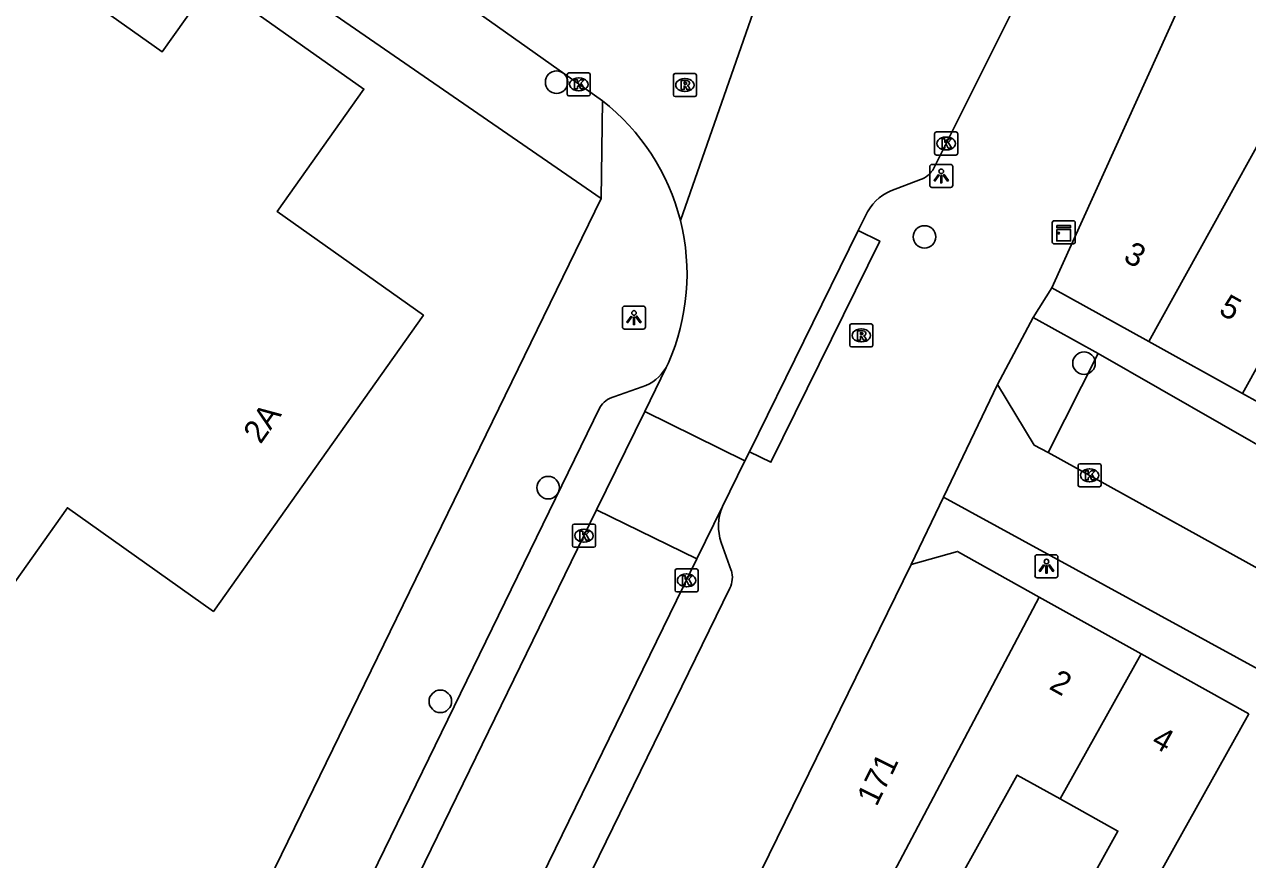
# Model space of a CAD drawing. Extents: x 160107 to 160928, y 382056 to 382918.
# Drawn here: x 160268.4 to 160321.6, y 382212 to 382248.3 of the extents above; entities that cross this region are included whole.
import ezdxf

# ---------------------------------------------------------------- set-up
doc = ezdxf.new("R2010")
doc.units = 0
for name, color, linetype in [('IMGEO_Boom', 7, 'Continuous'), ('IMGEO_Kast', 7, 'Continuous'), ('IMGEO_Kolk', 7, 'Continuous'), ('IMGEO_Lichtpunt', 7, 'Continuous'), ('IMGEO_Pand', 7, 'Continuous'), ('IMGEO_Pand_nummerreeks', 7, 'Continuous'), ('IMGEO_Parkeervlak_open', 7, 'Continuous'), ('IMGEO_Rijbaan_lokaal_open', 7, 'Continuous'), ('IMGEO_Rioolput', 7, 'Continuous'), ('IMGEO_Voetpad_open', 7, 'Continuous'), ('IMGEO_Woonerf_open', 7, 'Continuous')]:
    doc.layers.add(name, color=color, linetype=linetype)

msp = doc.modelspace()

# ---------------------------------------------------------------- linework, layer by layer
at = {"layer": 'IMGEO_Boom'}
for centre in [(160291.537, 382245.757), (160307.521, 382239.035), (160314.452, 382233.55), (160291.168, 382228.146), (160286.485, 382218.864)]:
    msp.add_circle(centre, 0.489, dxfattribs=at)
at = {"layer": 'IMGEO_Kast'}
for p, q in [((160313.072, 382238.813), (160313.072, 382239.654)), ((160313.072, 382239.654), (160313.072, 382238.813)), ((160313.147, 382239.738), (160313.988, 382239.738)), ((160313.988, 382239.738), (160313.147, 382239.738)), ((160314.072, 382239.663), (160314.072, 382238.822)), ((160314.072, 382238.822), (160314.072, 382239.663)), ((160313.997, 382238.738), (160313.156, 382238.738)), ((160313.156, 382238.738), (160313.997, 382238.738))]:
    msp.add_line(p, q, dxfattribs=at)
for points in [[(160313.267, 382239.528), (160313.867, 382239.528), (160313.867, 382239.443), (160313.267, 382239.443), (160313.267, 382239.528)], [(160313.267, 382239.353), (160313.867, 382239.353), (160313.867, 382238.864), (160313.267, 382238.864), (160313.267, 382239.353)]]:
    msp.add_lwpolyline(points, dxfattribs=at)
msp.add_circle((160313.351, 382239.202), 0.0377, dxfattribs=at)
for centre, start, end in [((160313.15, 382239.66), 92.4484, 184.2845), ((160313.15, 382239.66), 92.4484, 184.2845), ((160313.994, 382239.66), 2.4484, 94.2845), ((160313.994, 382239.66), 2.4484, 94.2845), ((160313.15, 382238.816), 182.4484, 274.2845), ((160313.15, 382238.816), 182.4484, 274.2845), ((160313.994, 382238.816), 272.4484, 4.2845), ((160313.994, 382238.816), 272.4484, 4.2845)]:
    msp.add_arc(centre, 0.0779, start, end, dxfattribs=at)
at = {"layer": 'IMGEO_Kolk'}
for p, q in [((160291.999, 382245.236), (160291.999, 382246.088)), ((160292.074, 382246.162), (160292.926, 382246.162)), ((160292.487, 382245.942), (160292.512, 382245.942)), ((160293, 382246.088), (160293, 382245.236)), ((160292.51, 382245.382), (160292.485, 382245.382)), ((160292.926, 382245.162), (160292.074, 382245.162)), ((160307.962, 382242.667), (160307.962, 382243.519)), ((160308.037, 382243.593), (160308.889, 382243.593)), ((160308.45, 382243.373), (160308.475, 382243.373)), ((160308.963, 382243.519), (160308.963, 382242.667)), ((160308.473, 382242.813), (160308.448, 382242.813)), ((160308.889, 382242.593), (160308.037, 382242.593)), ((160314.195, 382228.256), (160314.195, 382229.108)), ((160314.27, 382229.182), (160315.122, 382229.182)), ((160314.683, 382228.962), (160314.708, 382228.962)), ((160315.196, 382229.108), (160315.196, 382228.256)), ((160314.706, 382228.402), (160314.681, 382228.402)), ((160315.122, 382228.182), (160314.27, 382228.182)), ((160292.226, 382225.634), (160292.226, 382226.486)), ((160292.301, 382226.56), (160293.153, 382226.56)), ((160292.714, 382226.34), (160292.739, 382226.34)), ((160293.227, 382226.486), (160293.227, 382225.634)), ((160292.737, 382225.78), (160292.712, 382225.78)), ((160293.153, 382225.56), (160292.301, 382225.56)), ((160296.683, 382223.691), (160296.683, 382224.543)), ((160296.758, 382224.617), (160297.61, 382224.617)), ((160297.171, 382224.397), (160297.196, 382224.397)), ((160297.684, 382224.543), (160297.684, 382223.691)), ((160297.61, 382223.617), (160296.758, 382223.617)), ((160297.194, 382223.837), (160297.169, 382223.837))]:
    msp.add_line(p, q, dxfattribs=at)
for points in [[(160291.999, 382245.236), (160291.999, 382246.088)], [(160292.074, 382246.162), (160292.926, 382246.162)], [(160293, 382246.088), (160293, 382245.236)], [(160292.32, 382245.862), (160292.443, 382245.862), (160292.443, 382245.711), (160292.573, 382245.862), (160292.737, 382245.862), (160292.591, 382245.711), (160292.744, 382245.462), (160292.592, 382245.462), (160292.507, 382245.626), (160292.443, 382245.559), (160292.443, 382245.462), (160292.32, 382245.462), (160292.32, 382245.862)], [(160292.926, 382245.162), (160292.074, 382245.162)], [(160307.962, 382242.667), (160307.962, 382243.519)], [(160308.037, 382243.593), (160308.889, 382243.593)], [(160308.283, 382243.293), (160308.406, 382243.293), (160308.406, 382243.142), (160308.536, 382243.293), (160308.7, 382243.293), (160308.554, 382243.142), (160308.707, 382242.893), (160308.555, 382242.893), (160308.47, 382243.057), (160308.406, 382242.99), (160308.406, 382242.893), (160308.283, 382242.893), (160308.283, 382243.293)], [(160308.963, 382243.519), (160308.963, 382242.667)], [(160308.889, 382242.593), (160308.037, 382242.593)], [(160314.195, 382228.256), (160314.195, 382229.108)], [(160314.27, 382229.182), (160315.122, 382229.182)], [(160315.196, 382229.108), (160315.196, 382228.256)], [(160314.516, 382228.882), (160314.639, 382228.882), (160314.639, 382228.731), (160314.769, 382228.882), (160314.933, 382228.882), (160314.787, 382228.731), (160314.94, 382228.482), (160314.788, 382228.482), (160314.703, 382228.646), (160314.639, 382228.579), (160314.639, 382228.482), (160314.516, 382228.482), (160314.516, 382228.882)], [(160315.122, 382228.182), (160314.27, 382228.182)], [(160292.226, 382225.634), (160292.226, 382226.486)], [(160292.301, 382226.56), (160293.153, 382226.56)], [(160292.547, 382226.26), (160292.67, 382226.26), (160292.67, 382226.109), (160292.8, 382226.26), (160292.964, 382226.26), (160292.818, 382226.109), (160292.971, 382225.86), (160292.819, 382225.86), (160292.734, 382226.024), (160292.67, 382225.957), (160292.67, 382225.86), (160292.547, 382225.86), (160292.547, 382226.26)], [(160293.227, 382226.486), (160293.227, 382225.634)], [(160293.153, 382225.56), (160292.301, 382225.56)], [(160296.683, 382223.691), (160296.683, 382224.543)], [(160296.758, 382224.617), (160297.61, 382224.617)], [(160297.004, 382224.317), (160297.127, 382224.317), (160297.127, 382224.166), (160297.257, 382224.317), (160297.421, 382224.317), (160297.275, 382224.166), (160297.428, 382223.917), (160297.276, 382223.917), (160297.191, 382224.081), (160297.127, 382224.014), (160297.127, 382223.917), (160297.004, 382223.917), (160297.004, 382224.317)], [(160297.684, 382224.543), (160297.684, 382223.691)], [(160297.61, 382223.617), (160296.758, 382223.617)]]:
    msp.add_lwpolyline(points, dxfattribs=at)
for centre, start, end in [((160292.076, 382246.086), 91.552, 178.448), ((160292.076, 382246.086), 91.552, 178.448), ((160292.924, 382246.086), 1.552, 88.448), ((160292.924, 382246.086), 1.552, 88.448), ((160292.076, 382245.238), 181.552, 268.448), ((160292.076, 382245.238), 181.552, 268.448), ((160292.924, 382245.238), 271.552, 358.448), ((160292.924, 382245.238), 271.552, 358.448), ((160308.039, 382243.517), 91.552, 178.448), ((160308.039, 382243.517), 91.552, 178.448), ((160308.887, 382243.517), 1.552, 88.448), ((160308.887, 382243.517), 1.552, 88.448), ((160308.039, 382242.669), 181.552, 268.448), ((160308.039, 382242.669), 181.552, 268.448), ((160308.887, 382242.669), 271.552, 358.448), ((160308.887, 382242.669), 271.552, 358.448), ((160314.272, 382229.106), 91.552, 178.448), ((160314.272, 382229.106), 91.552, 178.448), ((160315.12, 382229.106), 1.552, 88.448), ((160315.12, 382229.106), 1.552, 88.448), ((160314.272, 382228.258), 181.552, 268.448), ((160314.272, 382228.258), 181.552, 268.448), ((160315.12, 382228.258), 271.552, 358.448), ((160315.12, 382228.258), 271.552, 358.448), ((160292.303, 382226.484), 91.552, 178.448), ((160292.303, 382226.484), 91.552, 178.448), ((160293.151, 382226.484), 1.552, 88.448), ((160293.151, 382226.484), 1.552, 88.448), ((160292.303, 382225.636), 181.552, 268.448), ((160292.303, 382225.636), 181.552, 268.448), ((160293.151, 382225.636), 271.552, 358.448), ((160293.151, 382225.636), 271.552, 358.448), ((160296.76, 382224.541), 91.552, 178.448), ((160296.76, 382224.541), 91.552, 178.448), ((160297.608, 382224.541), 1.552, 88.448), ((160297.608, 382224.541), 1.552, 88.448), ((160296.76, 382223.693), 181.552, 268.448), ((160296.76, 382223.693), 181.552, 268.448), ((160297.608, 382223.693), 271.552, 358.448), ((160297.608, 382223.693), 271.552, 358.448)]:
    msp.add_arc(centre, 0.0765, start, end, dxfattribs=at)
for centre, major_axis, ratio, start_param, end_param in [((160292.486, 382245.662), (-0.387, 0.002), 0.722429, 4.712389, 7.853982), ((160292.511, 382245.662), (-0.39, 0.002), 0.717154, 1.570796, 4.712389), ((160308.449, 382243.093), (-0.387, 0.002), 0.722429, 4.712389, 7.853982), ((160308.474, 382243.093), (-0.39, 0.002), 0.717154, 1.570796, 4.712389), ((160314.682, 382228.682), (-0.387, 0.002), 0.722429, 4.712389, 7.853982), ((160314.707, 382228.682), (-0.39, 0.002), 0.717154, 1.570796, 4.712389), ((160292.713, 382226.06), (-0.387, 0.002), 0.722429, 4.712389, 7.853982), ((160292.738, 382226.06), (-0.39, 0.002), 0.717154, 1.570796, 4.712389), ((160297.17, 382224.117), (-0.387, 0.002), 0.722429, 4.712389, 7.853982), ((160297.195, 382224.117), (-0.39, 0.002), 0.717154, 1.570796, 4.712389)]:
    msp.add_ellipse(centre, major_axis=major_axis, ratio=ratio, start_param=start_param, end_param=end_param, dxfattribs=at)
at = {"layer": 'IMGEO_Lichtpunt'}
for p, q in [((160308.653, 382242.182), (160307.845, 382242.182)), ((160308.653, 382242.182), (160307.845, 382242.182)), ((160307.751, 382242.087), (160307.751, 382241.28)), ((160307.751, 382242.087), (160307.751, 382241.28)), ((160308.747, 382241.28), (160308.747, 382242.087)), ((160308.747, 382241.28), (160308.747, 382242.087)), ((160307.845, 382241.186), (160308.653, 382241.186)), ((160307.845, 382241.186), (160308.653, 382241.186)), ((160294.399, 382235.935), (160294.399, 382235.128)), ((160294.399, 382235.935), (160294.399, 382235.128)), ((160295.301, 382236.03), (160294.493, 382236.03)), ((160295.301, 382236.03), (160294.493, 382236.03)), ((160295.395, 382235.128), (160295.395, 382235.935)), ((160295.395, 382235.128), (160295.395, 382235.935)), ((160294.493, 382235.034), (160295.301, 382235.034)), ((160294.493, 382235.034), (160295.301, 382235.034)), ((160313.225, 382225.231), (160312.417, 382225.231)), ((160313.225, 382225.231), (160312.417, 382225.231)), ((160312.323, 382225.136), (160312.323, 382224.329)), ((160312.323, 382225.136), (160312.323, 382224.329)), ((160313.319, 382224.329), (160313.319, 382225.136)), ((160313.319, 382224.329), (160313.319, 382225.136)), ((160312.417, 382224.235), (160313.225, 382224.235)), ((160312.417, 382224.235), (160313.225, 382224.235))]:
    msp.add_line(p, q, dxfattribs=at)
for points in [[(160308.125, 382241.751), (160308.164, 382241.723), (160307.976, 382241.461), (160307.938, 382241.488), (160308.125, 382241.751)], [(160308.227, 382241.703), (160308.274, 382241.703), (160308.274, 382241.381), (160308.227, 382241.381), (160308.227, 382241.703)], [(160308.337, 382241.723), (160308.375, 382241.75), (160308.562, 382241.488), (160308.523, 382241.46), (160308.337, 382241.723)], [(160294.773, 382235.599), (160294.812, 382235.571), (160294.624, 382235.309), (160294.586, 382235.336), (160294.773, 382235.599)], [(160294.875, 382235.551), (160294.922, 382235.551), (160294.922, 382235.229), (160294.875, 382235.229), (160294.875, 382235.551)], [(160294.985, 382235.571), (160295.023, 382235.598), (160295.21, 382235.336), (160295.171, 382235.308), (160294.985, 382235.571)], [(160312.697, 382224.8), (160312.736, 382224.772), (160312.548, 382224.51), (160312.51, 382224.537), (160312.697, 382224.8)], [(160312.799, 382224.752), (160312.846, 382224.752), (160312.846, 382224.43), (160312.799, 382224.43), (160312.799, 382224.752)], [(160312.909, 382224.772), (160312.947, 382224.799), (160313.134, 382224.537), (160313.095, 382224.509), (160312.909, 382224.772)]]:
    msp.add_lwpolyline(points, dxfattribs=at)
for centre in [(160308.25, 382241.885), (160294.898, 382235.733), (160312.822, 382224.934)]:
    msp.add_circle(centre, 0.0994, dxfattribs=at)
for centre, start, end in [((160307.845, 382242.087), 90, 180), ((160307.845, 382242.087), 90, 180), ((160308.653, 382242.087), 0, 90), ((160308.653, 382242.087), 0, 90), ((160307.845, 382241.28), 180, 270), ((160307.845, 382241.28), 180, 270), ((160308.653, 382241.28), 270, 0), ((160308.653, 382241.28), 270, 360), ((160294.493, 382235.935), 90, 180), ((160294.493, 382235.935), 90, 180), ((160295.301, 382235.935), 0, 90), ((160295.301, 382235.935), 0, 90), ((160294.493, 382235.128), 180, 270), ((160294.493, 382235.128), 180, 270), ((160295.301, 382235.128), 270, 0), ((160295.301, 382235.128), 270, 360), ((160312.417, 382225.136), 90, 180), ((160312.417, 382225.136), 90, 180), ((160313.225, 382225.136), 0, 90), ((160313.225, 382225.136), 0, 90), ((160312.417, 382224.329), 180, 270), ((160312.417, 382224.329), 180, 270), ((160313.225, 382224.329), 270, 0), ((160313.225, 382224.329), 270, 360)]:
    msp.add_arc(centre, 0.0946, start, end, dxfattribs=at)
at = {"layer": 'IMGEO_Pand'}
for points in [[(160319.853, 382251.839), (160319.021, 382250), (160313.06, 382236.826)], [(160276.751, 382250), (160283.166, 382245.457), (160279.394, 382240.141), (160285.753, 382235.63), (160276.629, 382222.77), (160270.28, 382227.274), (160266.508, 382221.957), (160262.395, 382224.799), (160260.069, 382226.406), (160246.848, 382235.539), (160245.406, 382235.324), (160238.876, 382240.069)], [(160270.283, 382250), (160274.4, 382247.08), (160276.475, 382250)], [(160317.268, 382234.495), (160323.812, 382246.308)], [(160321.345, 382232.236), (160325.176, 382239.154)], [(160313.06, 382236.826), (160317.268, 382234.495)], [(160317.268, 382234.495), (160321.345, 382232.236)], [(160325.421, 382229.978), (160321.345, 382232.236)], [(160312.51, 382223.394), (160308.957, 382225.373), (160306.947, 382224.801)], [(160306.947, 382224.801), (160299.069, 382208.718)], [(160303.434, 382206.287), (160303.632, 382206.617), (160306.971, 382212.926), (160312.51, 382223.394)], [(160316.935, 382220.93), (160312.51, 382223.394)], [(160313.423, 382214.624), (160316.935, 382220.93)], [(160316.935, 382220.93), (160321.607, 382218.327)], [(160321.607, 382218.327), (160315.45, 382207.27)], [(160313.423, 382214.624), (160311.554, 382215.665), (160307.391, 382208.191), (160305.645, 382205.056)], [(160315.45, 382207.27), (160313.281, 382208.478), (160315.927, 382213.23), (160313.423, 382214.624)]]:
    msp.add_lwpolyline(points, dxfattribs=at)
at = {"layer": 'IMGEO_Parkeervlak_open'}
for points in [[(160312.897, 382229.679), (160315.073, 382233.968)], [(160331.022, 382219.661), (160324.21, 382223.423), (160312.897, 382229.679)]]:
    msp.add_lwpolyline(points, dxfattribs=at)
at = {"layer": 'IMGEO_Rijbaan_lokaal_open'}
for points in [[(160270.914, 382260.88), (160274.913, 382258.023), (160286.371, 382250), (160288.021, 382248.834), (160293.524, 382244.948)], [(160307.928, 382242.026), (160311.913, 382250), (160312.565, 382251.304), (160314.231, 382254.699)], [(160300.493, 382250), (160296.914, 382239.751)], [(160306.065, 382241.044), (160307.344, 382241.524)], [(160304.645, 382239.317), (160304.957, 382239.95)], [(160299.914, 382229.705), (160304.645, 382239.317)], [(160296.294, 382233.367), (160295.364, 382231.46)], [(160296.392, 382233.568), (160296.294, 382233.367)], [(160295.364, 382231.46), (160293.276, 382227.177)], [(160295.364, 382231.46), (160299.721, 382229.314)], [(160299.721, 382229.314), (160299.914, 382229.705)], [(160298.74, 382227.321), (160299.721, 382229.314)], [(160297.633, 382225.052), (160298.74, 382227.321)], [(160281.398, 382202.817), (160293.276, 382227.177)], [(160293.276, 382227.177), (160297.633, 382225.052)], [(160297.633, 382225.052), (160269.244, 382166.896)]]:
    msp.add_lwpolyline(points, dxfattribs=at)
for centre, radius, start, end in [((160287.66, 382237.419), 9.543, 14.1445, 52.0883), ((160306.964, 382242.557), 1.101, 290.2117, 331.1523), ((160306.929, 382239.061), 2.163, 113.5412, 155.7303), ((160287.668, 382237.418), 9.536, 336.1869, 14.1616)]:
    msp.add_arc(centre, radius, start, end, dxfattribs=at)
at = {"layer": 'IMGEO_Rioolput'}
for p, q in [((160296.611, 382245.206), (160296.611, 382246.058)), ((160296.686, 382246.132), (160297.538, 382246.132)), ((160297.099, 382245.912), (160297.124, 382245.912)), ((160297.612, 382246.058), (160297.612, 382245.206)), ((160297.538, 382245.132), (160296.686, 382245.132)), ((160297.122, 382245.352), (160297.097, 382245.352)), ((160304.274, 382234.331), (160304.274, 382235.183)), ((160304.349, 382235.257), (160305.201, 382235.257)), ((160304.762, 382235.037), (160304.787, 382235.037)), ((160305.275, 382235.183), (160305.275, 382234.331)), ((160305.201, 382234.257), (160304.349, 382234.257)), ((160304.785, 382234.477), (160304.76, 382234.477))]:
    msp.add_line(p, q, dxfattribs=at)
for points in [[(160296.611, 382245.206), (160296.611, 382246.058)], [(160296.686, 382246.132), (160297.538, 382246.132)], [(160297.612, 382246.058), (160297.612, 382245.206)], [(160297.2, 382245.83), (160296.948, 382245.832), (160296.948, 382245.432)], [(160296.948, 382245.432), (160297.072, 382245.432), (160297.072, 382245.594), (160297.083, 382245.594)], [(160297.126, 382245.751), (160297.072, 382245.751), (160297.072, 382245.67)], [(160297.072, 382245.67), (160297.124, 382245.67)], [(160297.13, 382245.565), (160297.201, 382245.432), (160297.341, 382245.432), (160297.276, 382245.558)], [(160297.538, 382245.132), (160296.686, 382245.132)], [(160304.274, 382234.331), (160304.274, 382235.183)], [(160304.349, 382235.257), (160305.201, 382235.257)], [(160304.863, 382234.955), (160304.611, 382234.957), (160304.611, 382234.557)], [(160304.789, 382234.876), (160304.735, 382234.876), (160304.735, 382234.795)], [(160304.735, 382234.795), (160304.787, 382234.795)], [(160305.275, 382235.183), (160305.275, 382234.331)], [(160305.201, 382234.257), (160304.349, 382234.257)], [(160304.611, 382234.557), (160304.735, 382234.557), (160304.735, 382234.719), (160304.746, 382234.719)], [(160304.793, 382234.69), (160304.864, 382234.557), (160305.004, 382234.557), (160304.939, 382234.683)]]:
    msp.add_lwpolyline(points, dxfattribs=at)
for centre, radius, start, end in [((160296.688, 382246.056), 0.0765, 91.552, 178.448), ((160296.688, 382246.056), 0.0765, 91.552, 178.448), ((160297.536, 382246.056), 0.0765, 1.552, 88.448), ((160297.536, 382246.056), 0.0765, 1.552, 88.448), ((160297.082, 382245.541), 0.0533, 26.0293, 88.6989), ((160297.108, 382245.859), 0.19, 274.7715, 282.9687), ((160297.132, 382245.655), 0.0964, 77.0061, 93.1865), ((160297.146, 382245.712), 0.0378, 276.6634, 79.6772), ((160297.199, 382245.72), 0.109, 350.3612, 89.416), ((160297.197, 382245.72), 0.112, 277.5842, 350.9817), ((160297.181, 382245.505), 0.108, 29.5134, 73.7905), ((160296.688, 382245.208), 0.0765, 181.552, 268.448), ((160296.688, 382245.208), 0.0765, 181.552, 268.448), ((160297.536, 382245.208), 0.0765, 271.552, 358.448), ((160297.536, 382245.208), 0.0765, 271.552, 358.448), ((160304.351, 382235.181), 0.0765, 91.552, 178.448), ((160304.351, 382235.181), 0.0765, 91.552, 178.448), ((160304.771, 382234.984), 0.19, 274.7715, 282.9687), ((160304.795, 382234.78), 0.0964, 77.0061, 93.1865), ((160304.809, 382234.837), 0.0378, 276.6634, 79.6772), ((160304.862, 382234.845), 0.109, 350.3612, 89.416), ((160304.86, 382234.845), 0.112, 277.5842, 350.9817), ((160304.844, 382234.63), 0.108, 29.5134, 73.7905), ((160305.199, 382235.181), 0.0765, 1.552, 88.448), ((160305.199, 382235.181), 0.0765, 1.552, 88.448), ((160304.351, 382234.333), 0.0765, 181.552, 268.448), ((160304.351, 382234.333), 0.0765, 181.552, 268.448), ((160304.745, 382234.666), 0.0533, 26.0293, 88.6989), ((160305.199, 382234.333), 0.0765, 271.552, 358.448), ((160305.199, 382234.333), 0.0765, 271.552, 358.448)]:
    msp.add_arc(centre, radius, start, end, dxfattribs=at)
for centre, major_axis, ratio, start_param, end_param in [((160297.098, 382245.632), (-0.387, 0.002), 0.722429, 4.712389, 7.853982), ((160297.123, 382245.632), (-0.39, 0.002), 0.717154, 1.570796, 4.712389), ((160304.761, 382234.757), (-0.387, 0.002), 0.722429, 4.712389, 7.853982), ((160304.786, 382234.757), (-0.39, 0.002), 0.717154, 1.570796, 4.712389)]:
    msp.add_ellipse(centre, major_axis=major_axis, ratio=ratio, start_param=start_param, end_param=end_param, dxfattribs=at)
at = {"layer": 'IMGEO_Voetpad_open'}
for points in [[(160293.473, 382240.701), (160280, 382250), (160272.637, 382255.213), (160267.134, 382259.083), (160265.134, 382258.534)], [(160293.524, 382244.948), (160293.473, 382240.701)], [(160257.348, 382166.641), (160293.473, 382240.701)], [(160304.645, 382239.317), (160305.578, 382238.858), (160300.847, 382229.246), (160299.914, 382229.705)], [(160313.06, 382236.826), (160312.243, 382235.532)], [(160310.692, 382232.625), (160312.243, 382235.532)], [(160312.243, 382235.532), (160315.073, 382233.968)], [(160315.073, 382233.968), (160336.5, 382221.696)], [(160310.692, 382232.625), (160308.347, 382227.725)], [(160294.023, 382232.095), (160295.251, 382232.524)], [(160281.031, 382206.223), (160293.417, 382231.624)], [(160308.347, 382227.725), (160306.947, 382224.801)], [(160308.347, 382227.725), (160329.18, 382216.354)], [(160299.128, 382224.548), (160298.692, 382225.76)], [(160287.705, 382200.526), (160299.066, 382223.777)]]:
    msp.add_lwpolyline(points, dxfattribs=at)
for centre, radius, start, end in [((160294.709, 382234.262), 1.821, 287.3345, 330.5589), ((160294.293, 382231.123), 1.009, 105.5025, 150.2081), ((160300.774, 382226.477), 2.202, 157.4736, 199.0039), ((160298.101, 382224.243), 1.072, 334.2506, 16.5543)]:
    msp.add_arc(centre, radius, start, end, dxfattribs=at)
at = {"layer": 'IMGEO_Woonerf_open'}
msp.add_lwpolyline([(160312.897, 382229.679), (160312.288, 382229.996), (160310.692, 382232.625)], dxfattribs=at)

# ---------------------------------------------------------------- texts
at = {"layer": 'IMGEO_Pand_nummerreeks'}
for s, rotation, p in [('3', 331.0141, (160316.112, 382238.015)), ('5', 331.0141, (160320.258, 382235.719)), ('2A', 54.6448, (160278.67, 382230.002)), ('2', 330.8823, (160312.889, 382219.428)), ('4', 330.8833, (160317.327, 382216.957)), ('171', 63.902, (160305.436, 382214.263))]:
    msp.add_text(s, height=1, rotation=rotation, dxfattribs=at).set_placement(p)

doc.saveas('drawing.dxf')
